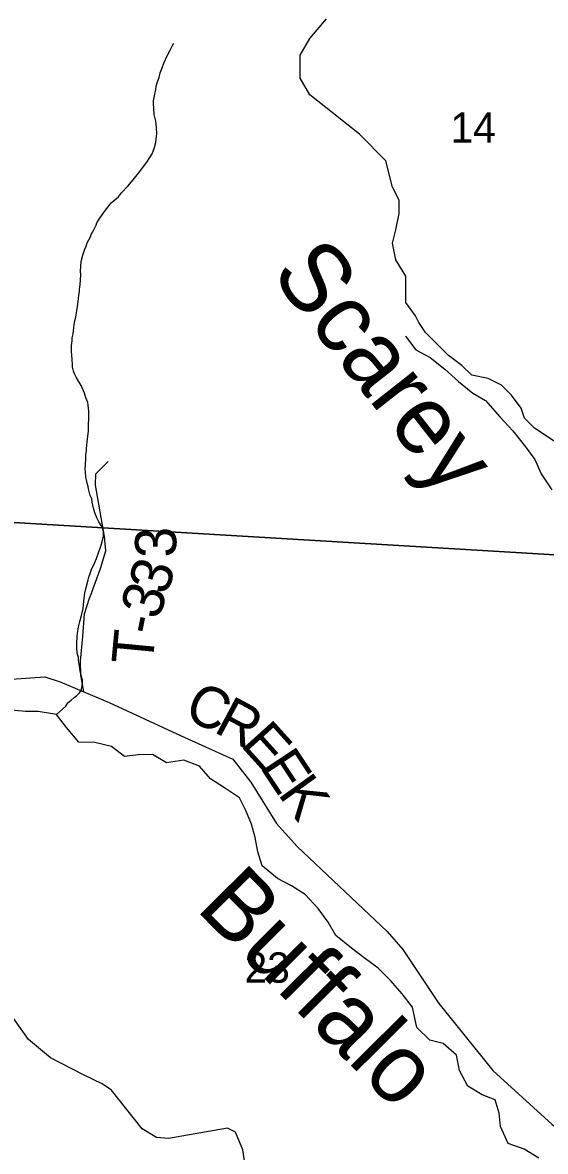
# Model space of a CAD drawing. Extents: x 1949938.81 to 1949945.61, y 152207.65 to 152214.09.
# Drawn here: x 1949943.741 to 1949944.46, y 152211.223 to 152212.776 of the extents above; entities that cross this region are included whole.
import ezdxf

# ---------------------------------------------------------------- set-up
doc = ezdxf.new("R2010")
doc.units = 0
for name, color, linetype in [('GM_X_County_Road', 7, 'Continuous'), ('GM_X_County_Road_Text', 7, 'Continuous'), ('GM_X_Minor_River', 7, 'Continuous'), ('GM_X_Minor_River_Text', 7, 'Continuous'), ('GM_X_Section', 7, 'Continuous'), ('GM_X_Section_Text', 7, 'Continuous'), ('GM_X_Township_Road', 7, 'Continuous'), ('GM_X_Township_Road_Text', 7, 'Continuous')]:
    doc.layers.add(name, color=color, linetype=linetype)

msp = doc.modelspace()

# ---------------------------------------------------------------- linework, layer by layer
at = {"layer": 'GM_X_County_Road'}
for points in [[(1949943.7253, 152211.8724), (1949943.7713, 152211.8759), (1949943.7925, 152211.8688), (1949943.8248, 152211.8553), (1949943.8598, 152211.8405), (1949943.959, 152211.7945), (1949944.0299, 152211.7626), (1949944.0547, 152211.7307), (1949944.0901, 152211.674), (1949944.1184, 152211.6421), (1949944.2424, 152211.5252), (1949944.2637, 152211.5004), (1949944.3132, 152211.426), (1949944.3876, 152211.3339), (1949944.4691, 152211.2594), (1949944.501, 152211.2382), (1949944.5506, 152211.224), (1949944.6249, 152211.1992)], [(1949944.0481, 152211.1938), (1949944.0481, 152211.1943), (1949944.0437, 152211.2246), (1949944.0338, 152211.2489), (1949944.0225, 152211.2546), (1949943.9414, 152211.2402), (1949943.9251, 152211.2417), (1949943.9054, 152211.2535), (1949943.863, 152211.3067), (1949943.8501, 152211.3154), (1949943.8244, 152211.328), (1949943.7793, 152211.3512), (1949943.749, 152211.3766), (1949943.6543, 152211.5096), (1949943.6025, 152211.5897), (1949943.5635, 152211.6585), (1949943.5517, 152211.6824), (1949943.5415, 152211.7117), (1949943.5373, 152211.7447), (1949943.5305, 152211.769)]]:
    msp.add_lwpolyline(points, dxfattribs=at)
at = {"layer": 'GM_X_Minor_River'}
for points in [[(1949943.8206, 152212.4286), (1949943.8203, 152212.4347), (1949943.8208, 152212.4407), (1949943.8213, 152212.4476), (1949943.8234, 152212.4563), (1949943.8262, 152212.4642), (1949943.8281, 152212.4687), (1949943.8297, 152212.4733), (1949943.834, 152212.4812), (1949943.8349, 152212.4846), (1949943.8388, 152212.491), (1949943.8419, 152212.4974), (1949943.8427, 152212.5008), (1949943.8462, 152212.5056), (1949943.8501, 152212.5116), (1949943.8548, 152212.518), (1949943.8586, 152212.5225), (1949943.8625, 152212.5281), (1949943.8725, 152212.5363), (1949943.8768, 152212.542), (1949943.8857, 152212.5513), (1949943.8907, 152212.5573), (1949943.8946, 152212.5622), (1949943.9, 152212.5689), (1949943.9046, 152212.5749), (1949943.9085, 152212.5801), (1949943.9116, 152212.5843), (1949943.9159, 152212.5907), (1949943.919, 152212.5955), (1949943.9202, 152212.5993), (1949943.9222, 152212.6042), (1949943.9238, 152212.6114), (1949943.9243, 152212.616), (1949943.9251, 152212.6197), (1949943.9256, 152212.6235), (1949943.9249, 152212.6308), (1949943.9243, 152212.6368), (1949943.924, 152212.6406), (1949943.9219, 152212.6498), (1949943.9213, 152212.6589), (1949943.921, 152212.6639), (1949943.921, 152212.6684), (1949943.9215, 152212.673), (1949943.924, 152212.6843), (1949943.9244, 152212.6889), (1949943.9264, 152212.6945), (1949943.9284, 152212.7009), (1949943.9301, 152212.707), (1949943.9325, 152212.7138), (1949943.9352, 152212.7202), (1949943.94, 152212.7315), (1949943.9443, 152212.7394), (1949943.947, 152212.7447), (1949943.949, 152212.7481)], [(1949943.7873, 152211.8241), (1949943.8003, 152211.8353), (1949943.803, 152211.8398), (1949943.8077, 152211.8435), (1949943.8115, 152211.8473), (1949943.8153, 152211.8499), (1949943.8192, 152211.8536), (1949943.8215, 152211.857), (1949943.8228, 152211.8634), (1949943.8232, 152211.868), (1949943.8229, 152211.8718), (1949943.8219, 152211.876), (1949943.8204, 152211.8813), (1949943.8194, 152211.887), (1949943.8191, 152211.8905), (1949943.8177, 152211.8988), (1949943.8174, 152211.903), (1949943.816, 152211.9084), (1949943.8154, 152211.916), (1949943.8151, 152211.9209), (1949943.8157, 152211.9319), (1949943.8161, 152211.9353), (1949943.8174, 152211.9444), (1949943.8194, 152211.952), (1949943.8218, 152211.9603), (1949943.8239, 152211.9698), (1949943.8247, 152211.9754), (1949943.8253, 152211.9838), (1949943.8262, 152211.991), (1949943.8278, 152211.997), (1949943.831, 152212.0091), (1949943.8319, 152212.0129), (1949943.8338, 152212.0178), (1949943.8354, 152212.0235), (1949943.8398, 152212.0322), (1949943.8425, 152212.0386), (1949943.8457, 152212.048), (1949943.8473, 152212.0529), (1949943.8497, 152212.0597), (1949943.8513, 152212.0658), (1949943.8518, 152212.0692), (1949943.8519, 152212.0753), (1949943.8505, 152212.0806), (1949943.8486, 152212.084), (1949943.8457, 152212.089), (1949943.8435, 152212.0936), (1949943.8402, 152212.1013), (1949943.8381, 152212.1078), (1949943.8363, 152212.1162), (1949943.836, 152212.1207), (1949943.8338, 152212.1253), (1949943.8313, 152212.1345), (1949943.831, 152212.1379), (1949943.8296, 152212.1425), (1949943.8278, 152212.1509), (1949943.8272, 152212.1573), (1949943.8269, 152212.1619), (1949943.8274, 152212.168), (1949943.8279, 152212.1759), (1949943.8276, 152212.1816), (1949943.8285, 152212.1858), (1949943.8285, 152212.19), (1949943.8294, 152212.1991), (1949943.8303, 152212.207), (1949943.8312, 152212.2139), (1949943.8314, 152212.223), (1949943.8319, 152212.2309), (1949943.832, 152212.2343), (1949943.8317, 152212.2412), (1949943.8307, 152212.2499), (1949943.8304, 152212.2534), (1949943.8279, 152212.2599), (1949943.8257, 152212.266), (1949943.8213, 152212.2767), (1949943.8177, 152212.2828), (1949943.8144, 152212.2882), (1949943.8125, 152212.292), (1949943.8107, 152212.2966), (1949943.8093, 152212.302), (1949943.8094, 152212.3054), (1949943.8087, 152212.3126), (1949943.8082, 152212.324), (1949943.8078, 152212.3274), (1949943.8079, 152212.3316), (1949943.8088, 152212.3384), (1949943.8089, 152212.3422), (1949943.8101, 152212.3479), (1949943.8114, 152212.3562), (1949943.8123, 152212.3634), (1949943.8139, 152212.3714), (1949943.8148, 152212.3767), (1949943.8164, 152212.3854), (1949943.8169, 152212.3888), (1949943.8173, 152212.3926), (1949943.8178, 152212.3967), (1949943.8182, 152212.4013), (1949943.8191, 152212.4062), (1949943.8191, 152212.4096), (1949943.82, 152212.4149), (1949943.8205, 152212.4225), (1949943.8206, 152212.4286)], [(1949944.2674, 152212.3448), (1949944.2817, 152212.3258), (1949944.3013, 152212.3151), (1949944.3217, 152212.299), (1949944.3406, 152212.2823), (1949944.3602, 152212.2663), (1949944.3776, 152212.2563), (1949944.3972, 152212.2335), (1949944.4153, 152212.2144), (1949944.4326, 152212.1924), (1949944.4454, 152212.1748), (1949944.4544, 152212.1551), (1949944.4687, 152212.133)], [(1949943.7623, 152211.828), (1949943.7449, 152211.8281), (1949943.7207, 152211.8304)], [(1949944.4512, 152211.2133), (1949944.4308, 152211.2255), (1949944.4089, 152211.2332), (1949944.3984, 152211.2568), (1949944.3962, 152211.275), (1949944.391, 152211.2933), (1949944.3728, 152211.3002), (1949944.3532, 152211.3124), (1949944.3419, 152211.3337), (1949944.3375, 152211.355), (1949944.3194, 152211.371), (1949944.3012, 152211.3757), (1949944.2831, 152211.3932), (1949944.2771, 152211.4213), (1949944.2628, 152211.4396), (1949944.247, 152211.4579), (1949944.2297, 152211.4747), (1949944.2108, 152211.4892), (1949944.1934, 152211.5022), (1949944.1715, 152211.5197), (1949944.161, 152211.538), (1949944.1474, 152211.557), (1949944.1293, 152211.5761), (1949944.1105, 152211.5883), (1949944.0916, 152211.5982), (1949944.0704, 152211.6158), (1949944.0645, 152211.6348), (1949944.0608, 152211.6545), (1949944.0555, 152211.6728), (1949944.048, 152211.6918), (1949944.039, 152211.7093), (1949944.0186, 152211.723), (1949943.999, 152211.7353), (1949943.9839, 152211.7528), (1949943.9627, 152211.7612), (1949943.9385, 152211.7575), (1949943.9196, 152211.769), (1949943.8999, 152211.7683), (1949943.881, 152211.7661), (1949943.8629, 152211.7798), (1949943.8402, 152211.7852), (1949943.8182, 152211.786), (1949943.8009, 152211.8058), (1949943.7873, 152211.8241), (1949943.7623, 152211.828)]]:
    msp.add_lwpolyline(points, dxfattribs=at)
at = {"layer": 'GM_X_Section'}
for points in [[(1949944.8197, 152213.0519), (1949944.7648, 152212.0263), (1949943.6665, 152212.0918), (1949943.7308, 152213.1166)], [(1949943.6665, 152212.0918), (1949944.7648, 152212.0263), (1949944.7104, 152211.0185), (1949943.6063, 152211.0859)]]:
    msp.add_lwpolyline(points, close=True, dxfattribs=at)
at = {"layer": 'GM_X_Township_Road'}
for points in [[(1949944.4723, 152212.1999), (1949944.445, 152212.2181), (1949944.4314, 152212.2318), (1949944.4268, 152212.2454), (1949944.4132, 152212.2636), (1949944.3996, 152212.2772), (1949944.3814, 152212.2863), (1949944.3587, 152212.2908), (1949944.345, 152212.3044), (1949944.3269, 152212.3181), (1949944.295, 152212.3499), (1949944.2859, 152212.3635), (1949944.2814, 152212.3726), (1949944.2678, 152212.3908), (1949944.2678, 152212.4271), (1949944.2541, 152212.4499), (1949944.2496, 152212.4726), (1949944.2541, 152212.4908), (1949944.2587, 152212.5135), (1949944.2587, 152212.5317), (1949944.2496, 152212.5498), (1949944.2405, 152212.5862), (1949944.2042, 152212.6225), (1949944.136, 152212.677), (1949944.1224, 152212.6998), (1949944.1224, 152212.7316), (1949944.136, 152212.7543), (1949944.1587, 152212.7815)], [(1949943.8359, 152211.9921), (1949943.8479, 152212.0249), (1949943.8553, 152212.0492), (1949943.8534, 152212.0689), (1949943.8409, 152212.1395), (1949943.8416, 152212.1551), (1949943.8582, 152212.1723)], [(1949943.8248, 152211.8553), (1949943.8208, 152211.8782), (1949943.8204, 152211.8975), (1949943.8236, 152211.9313), (1949943.8258, 152211.9625), (1949943.8329, 152211.9838), (1949943.8359, 152211.992), (1949943.8359, 152211.9921)]]:
    msp.add_lwpolyline(points, dxfattribs=at)

# ---------------------------------------------------------------- texts
at = {"layer": 'GM_X_County_Road_Text'}
for s, rotation, p in [('C', 335.1199, (1949943.9605, 152211.8199)), ('R', 331.8333, (1949944.0021, 152211.8007)), ('E', 312.0311, (1949944.0392, 152211.7818)), ('E', 303.4892, (1949944.0662, 152211.752)), ('K', 305.6897, (1949944.091, 152211.7146))]:
    msp.add_text(s, height=0.0568, rotation=rotation, dxfattribs=at).set_placement(p)
at = {"layer": 'GM_X_Minor_River_Text'}
for s, height, rotation, p in [('Scarey', 0.09468, 308.1241, (1949944.0808, 152212.4299)), ('Buffalo', 0.09471, 314.8733, (1949943.9776, 152211.5561))]:
    msp.add_text(s, height=height, rotation=rotation, dxfattribs=at).set_placement(p)
at = {"layer": 'GM_X_Section_Text'}
for s, p in [('14', (1949944.3295, 152212.6108)), ('23', (1949944.0461, 152211.4547))]:
    msp.add_text(s, height=0.04186, rotation=0, dxfattribs=at).set_placement(p)
at = {"layer": 'GM_X_Township_Road_Text'}
for s, rotation, p in [('3', 91.1693, (1949943.9526, 152212.0402)), ('3', 72.2637, (1949943.939, 152211.9868)), ('3', 71.2116, (1949943.9273, 152211.9526)), ('-', 78.4472, (1949943.9232, 152211.9315)), ('T', 84.6136, (1949943.9194, 152211.8908))]:
    msp.add_text(s, height=0.0568, rotation=rotation, dxfattribs=at).set_placement(p)

doc.saveas('drawing.dxf')
